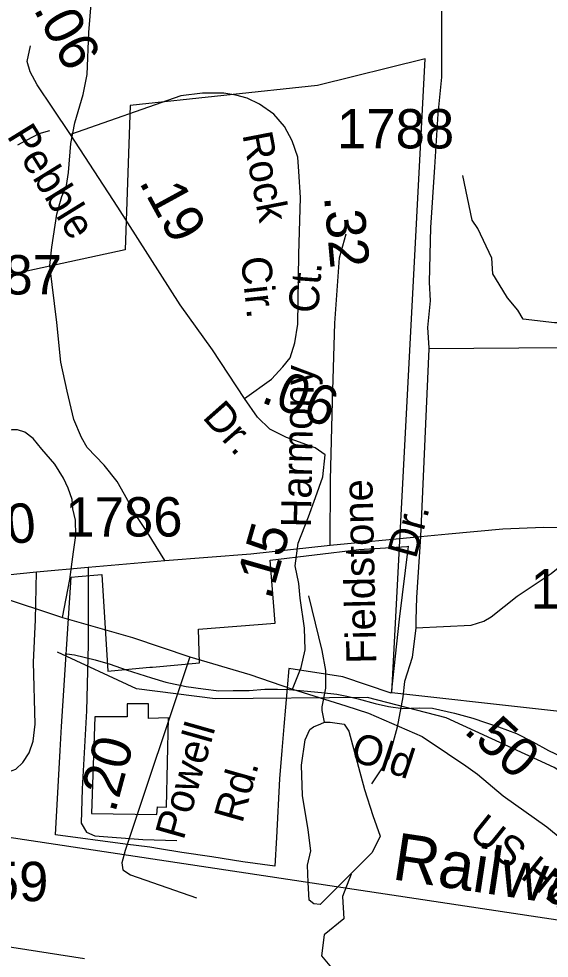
# Model space of a CAD drawing. Extents: x 2169602 to 2449496, y 721995 to 810662.
# Drawn here: x 2392905 to 2394589, y 763992 to 766975 of the extents above; entities that cross this region are included whole.
import ezdxf

# ---------------------------------------------------------------- set-up
doc = ezdxf.new("R2010")
doc.units = 0
doc.layers.add('Default', color=7, linetype='Continuous')

msp = doc.modelspace()

# ---------------------------------------------------------------- linework, layer by layer
at = {"layer": 'Default'}
msp.add_line((2394634.6, 765930.1), (2394206.5, 765926.8), dxfattribs=at)
for points in [[(2395691.7, 767254.8), (2395679.8, 766410.9), (2395124.3, 765278.6), (2395001.5, 764732.5), (2394089.4, 764834.3), (2394194.4, 766848), (2393853.2, 766763.1), (2393257.9, 766699.5), (2393242.5, 766241.6), (2392426, 766064.5)], [(2393367.9, 765255.2), (2393313.3, 765343.6), (2393277.2, 765398.2), (2393240.1, 765464.9), (2393217.2, 765505.3), (2393175.7, 765557.7), (2393122.2, 765613.9), (2393103.6, 765645.6), (2393079.6, 765702.4), (2393058.8, 765793), (2393038.1, 765884.2), (2393025, 766010.9), (2393003.1, 766191.6), (2393009.7, 766250), (2393025, 766354.9), (2393041.4, 766410.5), (2393056.6, 766446), (2393062.1, 766487.5), (2393069.7, 766579.3), (2393082.9, 766644.8), (2393109.1, 766734.9), (2393122.2, 766797.7), (2393127.6, 766932), (2393139.6, 767088.7)], [(2394246.9, 767060.3), (2394246.9, 766789.5), (2394234.9, 766673.7), (2394224, 766503.9), (2394212, 766312.3), (2394207.6, 766139.2), (2394210.9, 766079.7), (2394202.2, 765994.5), (2394206.3, 765930.5)], [(2393068.7, 766607.8), (2393013.2, 766691), (2392962.7, 766765.5), (2392941.3, 766807.1), (2392931.2, 766839.9), (2392942.3, 766889.2)], [(2393790.1, 766535.9), (2393772.5, 766587.6), (2393748.5, 766633), (2393714.4, 766672.1), (2393669, 766703.7), (2393629.9, 766722.6), (2393594.3, 766732.4), (2393556, 766738.5), (2393488.3, 766738.5), (2393419.5, 766730.9), (2393068.7, 766607.8)], [(2393001.7, 766619.7), (2392967.9, 766609.8), (2392929.9, 766589.6), (2392900.2, 766573.4)], [(2393621.1, 765769.1), (2393520.2, 765924.2), (2393416.8, 766066.7), (2393218.8, 766377), (2393068.7, 766607.8)], [(2393621.1, 765769.1), (2393706.9, 765830.9), (2393742.6, 765869.8), (2393766.6, 765898.2), (2393781.3, 765945.7), (2393790.1, 766004.9), (2393793.9, 766226.9), (2393799, 766407.3), (2393793.9, 766490.5), (2393790.1, 766535.9)], [(2394861.2, 765938.8), (2394847.2, 765950.6), (2394788.4, 765950.6), (2394773.4, 765948.5), (2394758.4, 765960.2), (2394717.7, 765928.1), (2394691, 765930.3), (2394682.4, 765942), (2394661, 765985.9), (2394643.9, 765995.6), (2394623.6, 766009.5), (2394605.4, 766009.5), (2394505.8, 766021.2), (2394488.7, 766050.1), (2394456.6, 766088.7), (2394429.8, 766132.5), (2394409.5, 766164.7), (2394406.3, 766215), (2394362.4, 766309.1), (2394344.2, 766335.9), (2394314.3, 766477.2)], [(2393893.1, 765303.2), (2393894.2, 765510.7), (2393900.8, 765760.2), (2393908.4, 766008.7), (2393922.6, 766215.6), (2393944.5, 766292.6)], [(2394206.3, 765930.5), (2394206.5, 765926.8), (2394180.3, 765331.1)], [(2393877.2, 765590), (2393845.6, 765612.7), (2393754.8, 765645.5), (2393701.8, 765672), (2393662.7, 765709.8), (2393621.1, 765769.1)], [(2393043.9, 765073.7), (2393066.8, 765194.9), (2393078.8, 765282.3), (2393085.4, 765334.7), (2393084.3, 765383.3), (2393076.6, 765419.3), (2393074.4, 765448.8), (2393061.3, 765484.9), (2393047.1, 765516.5), (2393018.8, 765560.8), (2392978.4, 765608.8), (2392950, 765642.7), (2392923.8, 765662.3), (2392900.8, 765670), (2392882.3, 765670), (2392861.5, 765664.5), (2392844, 765647), (2392828.7, 765624.1), (2392814.5, 765594.6)], [(2386341.5, 765606), (2386685.3, 765448.6), (2387371.5, 765146.4), (2387823.3, 764945.6), (2388085.7, 764838.9), (2388237.7, 764783.6), (2388424, 764732.4), (2388640.1, 764677.4), (2388810.3, 764648.1), (2388810.3, 764648.4), (2389850.9, 764490.4), (2391789.9, 764197.4), (2393113.8, 763990.4)], [(2393773.7, 764845.8), (2393801.5, 764915.2), (2393814.1, 764970.7), (2393811.6, 765040.1), (2393797.7, 765134.7), (2393793.9, 765181.3), (2393782.6, 765238.1), (2393791.4, 765310), (2393824.2, 765393.2), (2393846.9, 765455), (2393869.6, 765520.6), (2393877.2, 765590)], [(2389357.3, 765493.2), (2389701.1, 765335.8), (2390387.3, 765033.5), (2390839.1, 764832.8), (2391101.5, 764726.1), (2391253.5, 764670.8), (2391439.9, 764619.6), (2391655.9, 764564.6), (2391826.1, 764535.3), (2391826.2, 764535.5), (2392866.8, 764377.5), (2394805.7, 764084.6), (2396129.6, 763877.6)], [(2392474.6, 765169.5), (2392960.5, 765218.6), (2393125.4, 765233.3), (2393367.9, 765255.2), (2393641.1, 765276.3), (2393893.1, 765303.2), (2394180.3, 765331.1), (2394268.9, 765339.9), (2394441.7, 765355.3), (2394570.2, 765361.1), (2394658.6, 765360), (2394801.7, 765339.3), (2394906.5, 765306.5), (2395001.5, 765281.4), (2395427.4, 765163.5), (2395851.1, 765030.2), (2396059.7, 764960.9), (2396281.4, 764897), (2396463.7, 764835.9)], [(2394165, 765041.2), (2394340.9, 765049.9), (2394381.3, 765061.9), (2394404.2, 765076.1), (2394487.2, 765141.6), (2394595.3, 765213.7), (2394633.5, 765244.3), (2394649.9, 765265), (2394657.5, 765291.2), (2394661.9, 765322.9), (2394658.6, 765360)], [(2394180.3, 765331.1), (2394167.2, 765137.8), (2394165, 765066.8), (2394165, 765041.2)], [(2394112.2, 765068.8), (2394087.2, 764833.9), (2393933.5, 764885.7), (2393762, 764911.3), (2393746, 764727.1), (2393739.7, 764651.2), (2393732.2, 764561.9), (2393722.7, 764375.1), (2393717.5, 764284.1), (2393616.5, 764297.7), (2393517.2, 764313.7), (2393422.7, 764327.7), (2393351.2, 764338.8), (2393320.5, 764344.1), (2393242.7, 764354.2), (2393021.7, 764383.1), (2393036.5, 764651.2), (2393040.7, 764727.1), (2393070.5, 765202.1), (2393093, 765204.4), (2393168.2, 765210.2), (2393187.7, 764903.6), (2393242.7, 764908.6), (2393320.5, 764915.7), (2393329.5, 764916.5), (2393478.2, 764929.6), (2393475, 765037.2), (2393719, 765055.6), (2393703, 765255.6), (2393984.2, 765289.7), (2394136.7, 765299.4), (2394141.2, 765299.9), (2394112.2, 765068.8)], [(2394112.2, 765068.8), (2394087.2, 764833.9), (2393933.5, 764885.7), (2393762, 764911.3), (2393746, 764727.1), (2393739.7, 764651.2), (2393732.2, 764561.9), (2393722.7, 764375.1), (2393717.5, 764284.1), (2393616.5, 764297.7), (2393517.2, 764313.7), (2393422.7, 764327.7), (2393351.2, 764338.8), (2393320.5, 764344.1), (2393242.7, 764354.2), (2393021.7, 764383.1), (2393036.5, 764651.2), (2393040.7, 764727.1), (2393070.5, 765202.1), (2393093, 765204.4), (2393168.2, 765210.2), (2393187.7, 764903.6), (2393242.7, 764908.6), (2393320.5, 764915.7), (2393329.5, 764916.5), (2393478.2, 764929.6), (2393475, 765037.2), (2393719, 765055.6), (2393703, 765255.6), (2393984.2, 765289.7), (2394136.7, 765299.4), (2394141.2, 765299.9), (2394112.2, 765068.8)], [(2393125.4, 765233.3), (2393125.4, 764987.6), (2393120, 764777.4), (2393105.8, 764530.1), (2393102.5, 764420.3), (2393120, 764391.9), (2393146.2, 764379.9), (2393298, 764369), (2393406.1, 764365.7)], [(2392474.6, 765169.5), (2392486.6, 764923.8), (2392501.9, 764759.4), (2392516.1, 764684.6), (2392535.8, 764655.1), (2392566.3, 764632.2), (2392595.8, 764619.1), (2392649.3, 764607.1), (2392750.9, 764596.2), (2392841.5, 764584.1), (2392872.1, 764584.1), (2392895, 764591.8), (2392918, 764613.6), (2392937.6, 764644.2), (2392950.7, 764680.8), (2392956.2, 764735.4), (2392951.8, 764932), (2392957.3, 765066.8), (2392960.5, 765218.6)], [(2392835.3, 765143.1), (2393043.9, 765073.7), (2393265.6, 765009.8), (2393447.9, 764948.7)], [(2393875.5, 764741.2), (2393868, 764778.7), (2393868, 764790.5), (2393879.7, 764849.3), (2393879.7, 764905), (2393868, 764969.2), (2393825.2, 765142.6)], [(2394165, 765041.2), (2394154.1, 764947.2), (2394129, 764870.8), (2394123.5, 764821.7), (2394106.1, 764725.6), (2394093, 764679.1), (2394079.9, 764627.8), (2394048.2, 764580.9), (2394024.2, 764545.9)], [(2395601.5, 763586.1), (2395390.5, 763994), (2395156.5, 764234.9), (2394604.5, 764597.2), (2394261.5, 764755), (2394011.5, 764819.2), (2393528.4, 764815.9), (2393278.5, 764847.3), (2393027.5, 764963.9)], [(2393051.6, 764958.6), (2393057.6, 764958.9), (2393081.6, 764954.9), (2393147.4, 764939.3), (2393195.2, 764925.5), (2393245.8, 764907.7), (2393325.8, 764882.3), (2393371.5, 764868.5), (2393435.9, 764855), (2393489.8, 764847.3), (2393539.9, 764841.4), (2393585.8, 764841.7), (2393635.6, 764842.3), (2393685.7, 764846.5), (2393725.6, 764846.5), (2393763.6, 764844.8), (2393809.3, 764841.2), (2393865.7, 764835.5), (2393914.1, 764829.8), (2393945.9, 764823.8), (2393982, 764815.9), (2394035.9, 764800.4), (2394078.1, 764790.8), (2394123.9, 764785.1), (2394176.1, 764787.3), (2394217.8, 764785.5), (2394287.9, 764770), (2394346.1, 764754.3), (2394386.3, 764740.5), (2394428.2, 764726.5), (2394484.5, 764705), (2394536.4, 764679.3), (2394586.5, 764651.4), (2394644.9, 764623.9)], [(2393447.9, 764948.7), (2393242.6, 764333.9), (2393231.7, 764294.6), (2393235, 764272.7), (2393259, 764256.3), (2393468.7, 764183.2)], [(2393447.9, 764948.7), (2393637.9, 764892.4), (2393773.7, 764845.8)], [(2393773.7, 764845.8), (2393942.7, 764792.9), (2394014.6, 764770.2), (2394184.9, 764695.8), (2394265.6, 764641.5), (2394323.6, 764602.4), (2394361.5, 764575.9), (2394442.2, 764507.8), (2394580.9, 764409.5), (2394688.1, 764321.2), (2394934.1, 764123.2), (2395270.8, 763849.5), (2395654.9, 763535.4)], [(2393960, 764258.6), (2393932.2, 764187.9), (2393936.5, 764117.3), (2393874.4, 764065.9), (2393865.8, 763999.6), (2393908.6, 763948.2), (2393942.9, 763881.8), (2393949.3, 763830.5), (2393945, 763787.7), (2393437.7, 763845.4), (2393390.6, 763817.6), (2393339.3, 763834.7), (2393255.8, 763899), (2393033.2, 763933.2), (2392797.7, 763918.2), (2392635.1, 763877.6), (2392498.1, 763877.6)]]:
    msp.add_lwpolyline(points, dxfattribs=at)
for points in [[(2393146.4, 764758), (2393135.3, 764451.5), (2393342.8, 764448.2), (2393344.9, 764472.2), (2393373.3, 764471.1), (2393379.9, 764755), (2393316.6, 764753.4), (2393316.6, 764800.1), (2393249, 764800.1), (2393249, 764758)], [(2393863.7, 764735.9), (2393875.5, 764741.2), (2393893.7, 764741.2), (2393937.5, 764734.8), (2393952.5, 764712.3), (2394001.8, 764527.2), (2394028.5, 764444.8), (2394052.1, 764379.5), (2394026.4, 764327.1), (2393929, 764229.7), (2393861.6, 764162.2), (2393841.2, 764164.4), (2393826.2, 764176.1), (2393823, 764231.8), (2393820.9, 764287.5), (2393831.6, 764332.4), (2393823, 764399.8), (2393805.9, 764509), (2393802.7, 764605.3), (2393813.4, 764685.6), (2393828.4, 764717.7), (2393840.1, 764726.3)]]:
    msp.add_lwpolyline(points, close=True, dxfattribs=at)

# ---------------------------------------------------------------- texts
for s, height, rotation, p in [('.06', 125, 298.2762, (2392949.5, 767006.2)), ('Pebble', 95, 301.6706, (2392864.8, 766603)), ('Rock', 95, 280.9656, (2393614.2, 766607.6)), ('.19', 125, 298.656, (2393284.6, 766457.1)), ('.32', 125, 275.2418, (2393873.5, 766410.8)), ('Cir.', 95, 276.0559, (2393609.5, 766216.2)), ('Ct.', 95, 85.7138, (2393855.1, 766038.1)), ('Harmony', 95, 88.8448, (2393831.7, 765358.8)), ('.06', 125, 339.0909, (2393669.2, 765759)), ('Dr.', 95, 311.6133, (2393485.1, 765708.5)), ('Fieldstone', 95, 91.2578, (2394040.2, 764927.9)), ('1.30', 125, 5.1847, (2392639.3, 765286)), ('Dr.', 95, 74.7552, (2394165.2, 765257.4)), ('.15', 125, 73.9832, (2393703.9, 765127.1)), ('.50', 125, 317.6945, (2394314, 764710.6)), ('Powell', 95, 74.1938, (2393427.7, 764364.2)), ('Old', 95, 341.6513, (2393952.7, 764622.1)), ('.20', 125, 75.0129, (2393210.3, 764450.6)), ('Rd.', 95, 74.1938, (2393614, 764417.4)), ('US Hwy 70 W.', 95, 321.219, (2394328.3, 764381.9)), ('Railway', 150, 351.409, (2394086.5, 764243))]:
    msp.add_text(s, height=height, rotation=rotation, dxfattribs=at).set_placement(p)
for s, p in [('1788', (2393915.1, 766563.4)), ('1787', (2392669.9, 766099.7)), ('1786', (2393052.7, 765330.9)), ('1780', (2394529.6, 765102.3)), ('1759', (2392626.7, 764173))]:
    msp.add_text(s, height=125, dxfattribs=at).set_placement(p)

doc.saveas('drawing.dxf')
